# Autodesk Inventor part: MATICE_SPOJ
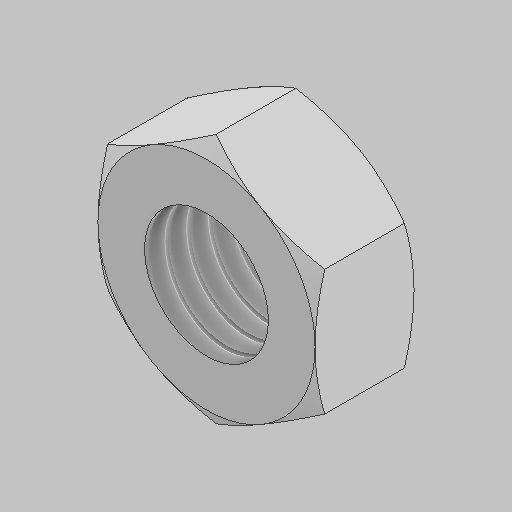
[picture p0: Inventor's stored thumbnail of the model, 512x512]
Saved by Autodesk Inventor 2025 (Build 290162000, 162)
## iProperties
Created: 2025-02
Part Number: MATICE_SPOJ
Material: Generic
Document SubType Name: Modeling
Designer: dansp
Density: 1 g/cm^3
Appearance: Default
Author: dansp
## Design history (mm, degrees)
sketch "Sketch1"
  geometry: L1 (0, 5.67)-(0, -5.67) reference; L2 (-4.91, 0)-(4.91, 0) reference; L3 (0, 4.05)-(3.507, 2.025); L4 (3.507, 2.025)-(3.507, -2.025); L5 (3.507, -2.025)-(0, -4.05); L6 (0, -4.05)-(-3.507, -2.025); L7 (-3.507, -2.025)-(-3.507, 2.025); L8 (-3.507, 2.025)-(0, 4.05); C1 r 2 at (0, 0); 2 further points
  constraints: 12 end point, 2 coincident, 1 centre point, 1 point on line, 13 other
  dimensions: "d0" = 8.1 distance of L5.end L3.start; "d1" = 4 diameter of C1
extrude "Extrusion1" new body sketch "Sketch1" stored distance "d2" = 3.2; taper "d3" = 0 deg
thread "Thread1" dims "d4" = 12.8, "d5" = 0
sketch "Sketch4"
  geometry: L1 (3.507, -1.6)-(0, -1.6) reference; L2 (3.507, -1.6)-(3.507, 1.6) reference; L3 (0, 1.6)-(3.507, 1.6) reference; L4 (0, -1.6)-(0, 1.6) reference; L5 (3.507, 1.6)-(6.507, -0.132); L6 (3.507, 1.6)-(6.507, 1.6); L7 (6.507, 1.6)-(6.507, -0.132); 1 further point
  constraints: 6 end point, 1 horizontal, 1 perpendicular
  dimensions: "d6" = 30 deg angle of L6 L5; "d7" = 3 distance from line of L2.end L7
revolve "Revolution1" sketch "Sketch4" stored, may be unused: angle "d8" = 90 deg
mirror "Mirror1"
body "Solid1"
node "Projected Loop2"
